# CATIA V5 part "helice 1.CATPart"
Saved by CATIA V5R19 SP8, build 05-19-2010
Part number: helice 1
Bounding box of the stored display mesh (mm): x -17.321 to 17.321, y -30 to 195, z -10 to 20
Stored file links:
  G:\EU_thinkMotion\CFAO_2010\MMS_groupe2\MMS_groupe2\A reprendre\splanchenault\Planchenault\helice 1.CATPart
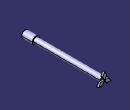
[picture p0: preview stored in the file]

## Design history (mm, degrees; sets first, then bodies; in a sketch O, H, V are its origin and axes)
Body1 (main body)
  Sketch1 on zx-plane, origin (0, 0, 0), H (-1, 0, 0), V (0, 0, 1)
    circle A1 centre (0, 0) radius 7.5
    radius A1 = 7.5
  Pad1: profile Sketch1, direction (0, 1, 0), length 190
  Sketch2 on start face of Pad1, origin (0, 0, 0), H (1, 0, 0), V (0, 0, 1)
    circle A1 centre (0, 0) radius 10
    radius A1 = 10
  Pad2: profile Sketch2, direction (0, -1, 0), length 30
  Sketch3 on end face of Pad1, origin (0, 190, 0), H (-1, 0, 0), V (0, 0, 1)
    point P1 (0, 0)
    point P2 (0, 0)
    construction line L1 (-27.3861, -15.8114) -> (27.3861, 15.8114)
    axis line L2 (35.7071, -20.6155) -> (-35.7071, 20.6155)
    line L3 (0, 0) -> (5.7735, 10)
    point P7 (5.7735, 10)
    line L4 (5.7735, 10) -> (0, 20)
    point P8 (0, 20)
    line L5 (0, 0) -> (-5.7735, 10)
    point P9 (-5.7735, 10)
    line L6 (-5.7735, 10) -> (0, 20)
    point P10 (-17.3205, -10)
    point P11 (-11.547, 0)
    line L7 (-11.547, 0) -> (-17.3205, -10)
    point P12 (-5.7735, -10)
    line L8 (-5.7735, -10) -> (-17.3205, -10)
    point P13 (0, 0)
    line L9 (0, 0) -> (-5.7735, -10)
    line L10 (0, 0) -> (-11.547, 0)
    point P14 (17.3205, -10)
    point P15 (5.7735, -10)
    line L11 (5.7735, -10) -> (17.3205, -10)
    point P16 (11.547, 0)
    line L12 (11.547, 0) -> (17.3205, -10)
    point P17 (0, 0)
    line L13 (0, 0) -> (11.547, 0)
    line L14 (0, 0) -> (5.7735, -10)
    angle L1 V = 60
    angle L2 V = 60
    coincidence: O P1, O P2, P1 P2, L1 O, P8 V
    perpendicularity: L3 L2, L4 L1
    parallelism: L5 L4, L6 L3
    symmetry: P8 P10 L2, P9 P11 L2, L6 L7 L2, P7 P12 L2, L4 L8 L2, O P13 L2, L3 L9 L2, L5 L10 L2, P8 P14 L1, P9 P15 L1, L6 L11 L1, P7 P16 L1, L4 L12 L1, O P17 L1, L3 L13 L1, L5 L14 L1
  Pad3: profile Sketch3, direction (0, 1, 0), length 5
